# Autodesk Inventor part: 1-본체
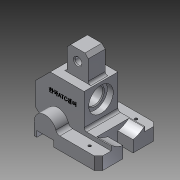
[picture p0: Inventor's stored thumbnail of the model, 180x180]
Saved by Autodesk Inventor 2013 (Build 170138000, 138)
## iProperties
Created: 2016-11
Part Number: 1-본체
Material: 알루미늄 6061
Document SubType Name: Modeling
Designer: default
Density: 2.71 g/cm^3
Mass: 462.906 g
Surface Area: 317.29 cm^2
Volume: 170.814 cm^3
Author: default
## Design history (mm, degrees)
sketch "스케치1"
  geometry: L1 (-38, -35)-(38, -35); L2 (38, -35)-(38, 35); L3 (38, 35)-(-38, 35); L4 (-38, 35)-(-38, -35); L5 (-38, -35)-(38, 35); L6 (38, -35)-(-38, 35); 1 further point
  constraints: 12 end point, 2 midpoint, 2 parallel, 1 horizontal, 1 perpendicular
  dimensions: "d0" = 76 distance of L1.start L1.end; "d2" = 70 distance of L3.end L1.start
extrude "돌출1" new body sketch "스케치1" distance "d3" = 15; taper "d4" = 0 deg
sketch "스케치2"
  geometry: L1 (0, 0)-(76, 0) reference; L2 (0, 0)-(0, 15) reference; L3 (3, 0)-(23, 0); L4 (23, 0)-(23, 7); L5 (23, 7)-(3, 7); L6 (3, 7)-(3, 0); 1 further point
  constraints: 8 end point, 2 parallel, 1 horizontal, 1 perpendicular, 1 point on line
  dimensions: "d5" = 3 distance between parallel lines of L6 L2; "d6" = 20 distance between parallel lines of L4 L6; "d7" = 7 distance between parallel lines of L1 L5
extrude "돌출2" cut sketch "스케치2" stored distance "d8" = 15; taper "d9" = 0 deg
sketch "스케치3"
  geometry: L1 (0, 0)-(76, 0) reference; L2 (0, -15)-(0, 0) reference; A1 r 13 centre (13, 0) between (26, 0) and (0, 0); 1 further point
  constraints: 2 point on circle, 2 point on line, 1 centre point, 1 end point
  dimensions: "d12" = 13 radius of A1
extrude "돌출3" join sketch "스케치3" distance "d14" = 70; taper "d15" = 0 deg
node "작업 평면1"
sketch "스케치4"
  geometry: L1 (-53, 0)-(-53, 7) reference; L2 (-53, 7)-(-73, 7) reference; L3 (-73, 7)-(-73, 0) reference; L4 (-73, 0)-(-76, 0) reference; L5 (-76, 0)-(-76, 15) reference; L6 (-50, 15)-(0, 15) reference; L7 (0, 15)-(0, 0) reference; L8 (0, 0)-(-53, 0) reference; L9 (-76, 12)-(-90, 12); L10 (-90, 12)-(-90, 42); L11 (-90, 42)-(-72, 60); L12 (-72, 60)-(-32, 60); L13 (-32, 60)-(-32, 20); L14 (-32, 20)-(0, 20); L15 (0, 20)-(0, 15); A1 r 13 centre (-63, 15) between (-50, 15) and (-76, 15) reference; 1 further point
  constraints: 14 end point, 5 parallel, 1 perpendicular, 1 point on line
  dimensions: "d16" = 45 deg angle of L12 L11; "d17" = 20 distance between parallel lines of L8 L14; "d18" = 48 distance between parallel lines of L9 L12; "d19" = 58 distance between parallel lines of L13 L10; "d20" = 18 distance from line of L11.end L10; "d21" = 60 distance between parallel lines of L4 L12; "d22" = 90 distance between parallel lines of L7 L10
extrude "돌출4" join sketch "스케치4" stored distance "d23" = 40; taper "d24" = 0 deg
sketch "스케치5"
  geometry: 2 further points
  constraints: 1 horizontal alignment
  dimensions: "d25" = 42 distance of point (60, 20) point (18, 20)
hole "구멍1" sketch "스케치5" at (18, 20) diameter "d26" = 20; stored, may be unused: countersink angle "d30" = 90 deg, drill point angle "d32" = 118 deg; dims "d27" = 6, "d28" = 29, "d29" = 7, "d31" = 8
chamfer "모따기1" distance "d33" = 1; stored, may be unused: second distance "d34" = 2, angle "d35" = 45 deg
sketch "스케치6"
  geometry: L1 (-72, 60)-(-32, 60) reference; L2 (-62, 60)-(-37, 60); L3 (-37, 60)-(-37, 90); L4 (-37, 90)-(-62, 90); L5 (-62, 90)-(-62, 60); L6 (-32, 56.5)-(-32, 27.5) reference; L7 (0, 0)-(-53, 0) reference; 1 further point
  constraints: 8 end point, 2 parallel, 1 horizontal, 1 perpendicular, 1 point on line
  dimensions: "d36" = 5 distance between parallel lines of L6 L3; "d37" = 25 distance of L3.end L4.end; "d38" = 90 distance between parallel lines of L7 L4
extrude "돌출5" join sketch "스케치6" stored distance "d39" = 20; taper "d40" = 0 deg
chamfer "모따기2" distance "d41" = 4; stored, may be unused: second distance "d42" = 2, angle "d43" = 45 deg
sketch "스케치7"
  geometry: L1 (-41, 90)-(-58, 90) reference; L2 (-53, 0)-(-53, 7) reference; L3 (-53, 7)-(-73, 7) reference; L4 (-73, 7)-(-73, 0) reference; L5 (-73, 0)-(-76, 0) reference; L6 (-76, 0)-(-76, 12) reference; L7 (-76, 12)-(-90, 12) reference; L8 (-90, 12)-(-90, 42) reference; L9 (-90, 42)-(-72, 60) reference; L10 (-72, 60)-(-62, 60) reference; L11 (-62, 60)-(-62, 86) reference; L12 (-62, 86)-(-58, 90) reference; L13 (-58, 90)-(-41, 90) reference; L14 (-41, 90)-(-37, 86) reference; L15 (-37, 86)-(-37, 60) reference; L16 (-37, 60)-(-32, 60) reference; L17 (-32, 60)-(-32, 52.5) reference; L18 (-32, 52.5)-(-39, 52.5) reference; L19 (-39, 52.5)-(-39, 46.583) reference; L20 (-40, 42)-(-90, 42) reference; L21 (0, 0)-(-53, 0) reference; L22 (0, 20)-(0, 0) reference; L23 (-32, 20)-(0, 20) reference; L24 (-32, 31.5)-(-32, 20) reference; L25 (-39, 31.5)-(-32, 31.5) reference; L26 (-39, 37.417)-(-39, 31.5) reference; L27 (-62, 60)-(-37, 60) reference; 3 further points
  constraints: 1 midpoint, 1 vertical alignment, 2 other
  dimensions: "d44" = 35 distance from line of L20 point (-49.5, 77)
hole "구멍2" sketch "스케치7" at (-49.5, 77) diameter "d45" = 8; stored, may be unused: countersink angle "d49" = 90 deg, drill point angle "d51" = 118 deg; dims "d46" = 6, "d47" = 4, "d48" = 2, "d50" = 8
chamfer "모따기3" distance "d52" = 1; stored, may be unused: second distance "d53" = 2, angle "d54" = 45 deg
sketch "스케치8"
  geometry: L1 (0, 0)-(0, 70) reference; L2 (0, 70)-(0, 0) reference; L3 (0, 0)-(-15, 0) reference; L4 (-15, 0)-(-15, 15) reference; L5 (-15, 15)-(-20, 15) reference; L6 (-20, 15)-(-20, 55) reference; L7 (-20, 55)-(-15, 55) reference; L8 (-15, 55)-(-15, 70) reference; L9 (-15, 70)-(0, 70) reference; C1 r 29 at (-42, 35); 1 further point
  constraints: 1 centre point
  dimensions: "d55" = 42 distance from line of L1 C1.centre; "d56" = 58 diameter of C1
extrude "돌출6" cut sketch "스케치8" distance "d57" = 18; taper "d58" = 0 deg
sketch "스케치9"
  geometry: L1 (0, 0)-(0, 70) reference; L2 (-13.627, 29)-(0, 29); L3 (-13.627, 41)-(0, 41); A1 r 29 centre (-42, 35) between (-20, 16.106) and (-20, 53.894) reference; 1 further point
  constraints: 4 end point, 2 perpendicular, 2 point on circle, 2 point on line
  dimensions: "d59" = 12 distance between parallel lines of L3 L2; "d60" = 6 distance from line of point (0, 35) L2
extrude "돌출7" cut sketch "스케치9" distance "d61" = 18; taper "d62" = 0 deg
chamfer "모따기4" distance "d63" = 5; stored, may be unused: second distance "d64" = 2, angle "d65" = 45 deg
chamfer "모따기5" distance "d66" = 4; stored, may be unused: second distance "d67" = 2, angle "d68" = 45 deg
sketch "스케치10"
  geometry: L1 (38, -30)-(38, -20) reference; L2 (38, 6)-(38, 30) reference; L3 (33, 35)-(-15, 35) reference; 3 further points
  dimensions: "d69" = 18 distance from line of L1 point (20, -27.5); "d70" = 18 distance from line of L2 point (20, 27.5); "d71" = 55 distance of point (20, -27.5) point (20, 27.5); "d72" = 7.5 distance from line of point (20, 27.5) L3
hole "구멍3" sketch "스케치10" at (20, -27.5), (20, 27.5) diameter "d73" = 3.242; stored, may be unused: countersink angle "d77" = 90 deg, drill point angle "d79" = 118 deg; dims "d74" = 6, "d75" = 4, "d76" = 2, "d78" = 8
node "작업 평면2"
sketch "스케치11"
  geometry: L1 (-32, 60)-(-72, 60) reference; L2 (-32, 20)-(-32, 60) reference; 2 further points
  constraints: 1 other
  dimensions: "d81" = 18 distance from line of point (-57, 42) L1; "d82" = 25 distance from line of L2 point (-57, 42)
feature "엠보싱1" sketch "스케치11" dims "d0" = 76, "d2" = 70, "d83" = 0.5, "d84" = 0
fillet "모깎기1" dims "d85" = 5
fillet "모깎기2" dims "d86" = 3
node "솔리드1"
node "절단 모서리 투영1"
node "절단 모서리 투영2"
node "절단 모서리 투영3"
other parameters: "d10" = 26
